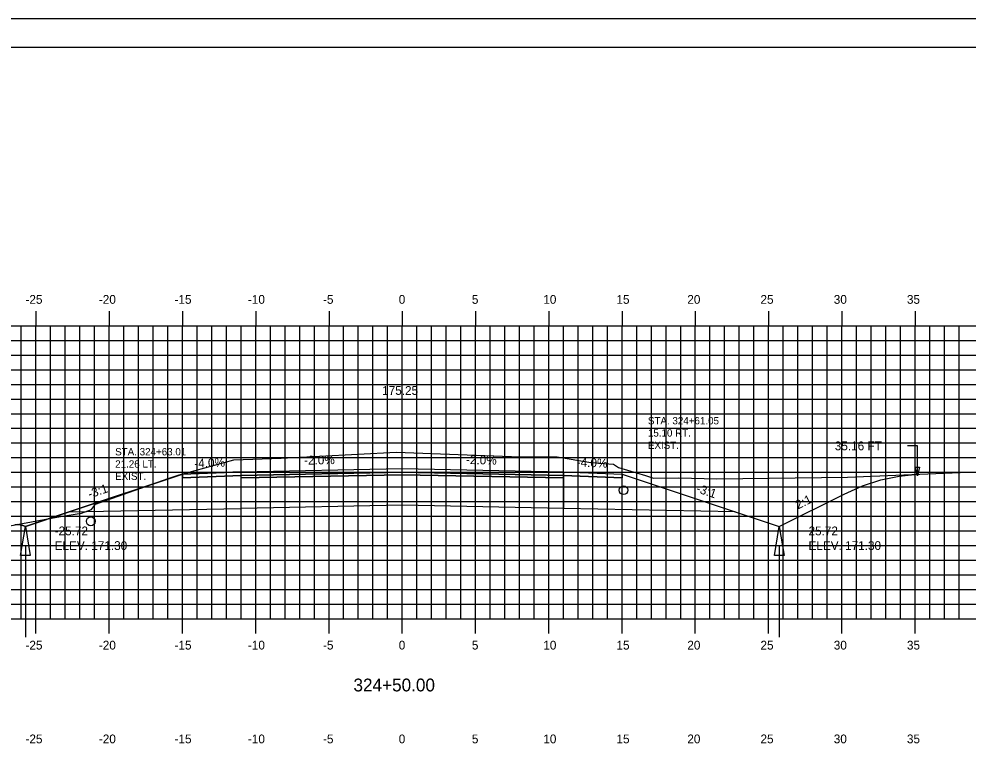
# Model space of a CAD drawing. Extents: x 1140315 to 1140485, y 608981 to 609091.
# Drawn here: x 1140372.3 to 1140437.1, y 609041.6 to 609091.3 of the extents above; entities that cross this region are included whole.
import ezdxf

# ---------------------------------------------------------------- set-up
doc = ezdxf.new("R2010")
doc.units = 0
for name, color, linetype in [('ANNOTATION', 7, 'Continuous'), ('BORDER', 7, 'Continuous'), ('D_Drainage_Ditch_Line', 7, 'Continuous'), ('D_Roadway_Centerline', 7, 'Continuous'), ('D_Roadway_Centerline_Text', 7, 'Continuous'), ('D_Roadway_Edge_Shoulder', 7, 'Continuous'), ('D_Roadway_Edge_TW', 7, 'Continuous'), ('D_Roadway_Pavement', 7, 'Continuous'), ('D_Roadway_SlopeLines', 7, 'Continuous'), ('D_Roadway_SubGrade', 7, 'Continuous'), ('D_Text_Monospaced', 7, 'Continuous'), ('D_Text_Standard', 7, 'Continuous'), ('H_V ANNOTATION', 7, 'Continuous'), ('MAJOR', 7, 'Continuous'), ('MINOR', 7, 'Continuous'), ('PLOT BOUNDARY', 7, 'Continuous'), ('S_Drainage_Invert', 7, 'Continuous'), ('S_Roadway_Centerline', 7, 'Continuous')]:
    doc.layers.add(name, color=color, linetype=linetype)

msp = doc.modelspace()

# ---------------------------------------------------------------- linework, layer by layer
msp.add_lwpolyline([(1140372.049, 609056.744), (1140372.227, 609056.762), (1140372.406, 609056.749), (1140372.585, 609056.706), (1140372.763, 609056.632), (1140375.763, 609057.632), (1140383.487, 609060.206), (1140383.488, 609060.206), (1140387.488, 609060.366), (1140398.488, 609060.586), (1140409.488, 609060.366), (1140413.488, 609060.206), (1140421.211, 609057.632), (1140424.211, 609056.632), (1140428.647, 609058.85), (1140429.897, 609059.403), (1140431.147, 609059.813), (1140432.397, 609060.079), (1140433.647, 609060.201)])
at = {"layer": 'BORDER'}
msp.add_lwpolyline([(1140323.488, 608984.335), (1140483.488, 608984.335), (1140483.488, 609089.335), (1140323.488, 609089.335)], close=True, dxfattribs=at)
at = {"layer": 'D_Drainage_Ditch_Line'}
for p, q in [((1140372.763, 609055.32), (1140372.763, 609049.076)), ((1140424.212, 609055.32), (1140424.211, 609049.076))]:
    msp.add_line(p, q, dxfattribs=at)
for points in [[(1140373.091, 609054.663), (1140372.435, 609054.663), (1140372.763, 609056.632)], [(1140424.54, 609054.663), (1140423.883, 609054.663), (1140424.211, 609056.632)]]:
    msp.add_lwpolyline(points, close=True, dxfattribs=at)
at = {"layer": 'D_Roadway_Edge_Shoulder'}
for points in [[(1140387.488, 609060.366), (1140383.488, 609060.206), (1140383.488, 609059.956), (1140387.488, 609060.116)], [(1140409.488, 609060.366), (1140413.488, 609060.206), (1140413.488, 609059.956), (1140409.488, 609060.116)]]:
    msp.add_lwpolyline(points, close=True, dxfattribs=at)
at = {"layer": 'D_Roadway_Edge_TW'}
msp.add_lwpolyline([(1140387.488, 609060.116), (1140387.488, 609060.366), (1140398.488, 609060.586), (1140409.488, 609060.366), (1140409.488, 609060.116), (1140398.488, 609060.336)], close=True, dxfattribs=at)
at = {"layer": 'D_Roadway_Pavement'}
msp.add_lwpolyline([(1140387.488, 609059.95), (1140387.488, 609060.116), (1140398.488, 609060.336), (1140409.488, 609060.116), (1140409.488, 609059.95), (1140398.488, 609060.17)], close=True, dxfattribs=at)
at = {"layer": 'D_Roadway_SlopeLines'}
for points in [[(1140424.211, 609056.632), (1140428.647, 609058.85), (1140429.897, 609059.403), (1140431.147, 609059.813), (1140432.397, 609060.079), (1140433.647, 609060.201)], [(1140375.763, 609057.632), (1140372.763, 609056.632)], [(1140421.211, 609057.632), (1140424.211, 609056.632)], [(1140372.763, 609056.632), (1140372.585, 609056.706), (1140372.406, 609056.749), (1140372.227, 609056.762), (1140372.049, 609056.744)]]:
    msp.add_lwpolyline(points, dxfattribs=at)
at = {"layer": 'D_Roadway_SubGrade'}
for points in [[(1140387.488, 609059.95), (1140387.488, 609060.116), (1140383.488, 609059.956), (1140383.488, 609060.206), (1140383.487, 609060.206), (1140375.763, 609057.632), (1140387.488, 609057.866)], [(1140387.488, 609057.866), (1140387.488, 609059.95), (1140398.488, 609060.17), (1140409.488, 609059.95), (1140409.488, 609057.866), (1140398.488, 609058.086)], [(1140409.488, 609059.95), (1140409.488, 609060.116), (1140413.488, 609059.956), (1140413.488, 609060.206), (1140413.488, 609060.206), (1140421.211, 609057.632), (1140409.488, 609057.866)]]:
    msp.add_lwpolyline(points, close=True, dxfattribs=at)
at = {"layer": 'D_Text_Standard'}
msp.add_lwpolyline([(1140433.647, 609060.1), (1140433.648, 609062.138), (1140432.968, 609062.138)], dxfattribs=at)
msp.add_lwpolyline([(1140433.647, 609060.1), (1140433.501, 609060.682), (1140433.793, 609060.682)], close=True, dxfattribs=at)
at = {"layer": 'MAJOR'}
for p, q in [((1140373.488, 609071.337), (1140373.488, 609070.335)), ((1140378.488, 609071.337), (1140378.488, 609070.335)), ((1140383.488, 609071.337), (1140383.488, 609070.335)), ((1140388.488, 609071.337), (1140388.488, 609070.335)), ((1140393.488, 609071.337), (1140393.488, 609070.335)), ((1140398.488, 609071.337), (1140398.488, 609070.335)), ((1140403.488, 609071.337), (1140403.488, 609070.335)), ((1140408.488, 609071.337), (1140408.488, 609070.335)), ((1140413.488, 609071.337), (1140413.488, 609070.335)), ((1140418.488, 609071.337), (1140418.488, 609070.335)), ((1140423.488, 609071.337), (1140423.488, 609070.335)), ((1140428.488, 609071.337), (1140428.488, 609070.335)), ((1140433.488, 609071.337), (1140433.488, 609070.335)), ((1140328.488, 609070.335), (1140468.488, 609070.335)), ((1140328.488, 609070.335), (1140468.488, 609070.335)), ((1140373.488, 609050.335), (1140373.488, 609070.335)), ((1140378.488, 609050.335), (1140378.488, 609070.335)), ((1140383.488, 609050.335), (1140383.488, 609070.335)), ((1140388.488, 609050.335), (1140388.488, 609070.335)), ((1140393.488, 609050.335), (1140393.488, 609070.335)), ((1140398.488, 609050.335), (1140398.488, 609070.335)), ((1140403.488, 609050.335), (1140403.488, 609070.335)), ((1140408.488, 609050.335), (1140408.488, 609070.335)), ((1140413.488, 609050.335), (1140413.488, 609070.335)), ((1140418.488, 609050.335), (1140418.488, 609070.335)), ((1140423.488, 609050.335), (1140423.488, 609070.335)), ((1140428.488, 609050.335), (1140428.488, 609070.335)), ((1140433.488, 609050.335), (1140433.488, 609070.335)), ((1140328.488, 609065.335), (1140468.488, 609065.335)), ((1140328.488, 609060.335), (1140468.488, 609060.335)), ((1140328.488, 609055.335), (1140468.488, 609055.335)), ((1140328.488, 609050.335), (1140468.488, 609050.335)), ((1140328.488, 609050.335), (1140468.488, 609050.335)), ((1140373.488, 609049.333), (1140373.488, 609050.335)), ((1140378.488, 609049.333), (1140378.488, 609050.335)), ((1140383.488, 609049.333), (1140383.488, 609050.335)), ((1140388.488, 609049.333), (1140388.488, 609050.335)), ((1140393.488, 609049.333), (1140393.488, 609050.335)), ((1140398.488, 609049.333), (1140398.488, 609050.335)), ((1140403.488, 609049.333), (1140403.488, 609050.335)), ((1140408.488, 609049.333), (1140408.488, 609050.335)), ((1140413.488, 609049.333), (1140413.488, 609050.335)), ((1140418.488, 609049.333), (1140418.488, 609050.335)), ((1140423.488, 609049.333), (1140423.488, 609050.335)), ((1140428.488, 609049.333), (1140428.488, 609050.335)), ((1140433.488, 609049.333), (1140433.488, 609050.335))]:
    msp.add_line(p, q, dxfattribs=at)
at = {"layer": 'MINOR'}
for p, q in [((1140372.488, 609050.335), (1140372.488, 609070.335)), ((1140374.488, 609050.335), (1140374.488, 609070.335)), ((1140375.488, 609050.335), (1140375.488, 609070.335)), ((1140376.488, 609050.335), (1140376.488, 609070.335)), ((1140377.488, 609050.335), (1140377.488, 609070.335)), ((1140379.488, 609050.335), (1140379.488, 609070.335)), ((1140380.488, 609050.335), (1140380.488, 609070.335)), ((1140381.488, 609050.335), (1140381.488, 609070.335)), ((1140382.488, 609050.335), (1140382.488, 609070.335)), ((1140384.488, 609050.335), (1140384.488, 609070.335)), ((1140385.488, 609050.335), (1140385.488, 609070.335)), ((1140386.488, 609050.335), (1140386.488, 609070.335)), ((1140387.488, 609050.335), (1140387.488, 609070.335)), ((1140389.488, 609050.335), (1140389.488, 609070.335)), ((1140390.488, 609050.335), (1140390.488, 609070.335)), ((1140391.488, 609050.335), (1140391.488, 609070.335)), ((1140392.488, 609050.335), (1140392.488, 609070.335)), ((1140394.488, 609050.335), (1140394.488, 609070.335)), ((1140395.488, 609050.335), (1140395.488, 609070.335)), ((1140396.488, 609050.335), (1140396.488, 609070.335)), ((1140397.488, 609050.335), (1140397.488, 609070.335)), ((1140399.488, 609050.335), (1140399.488, 609070.335)), ((1140400.488, 609050.335), (1140400.488, 609070.335)), ((1140401.488, 609050.335), (1140401.488, 609070.335)), ((1140402.488, 609050.335), (1140402.488, 609070.335)), ((1140404.488, 609050.335), (1140404.488, 609070.335)), ((1140405.488, 609050.335), (1140405.488, 609070.335)), ((1140406.488, 609050.335), (1140406.488, 609070.335)), ((1140407.488, 609050.335), (1140407.488, 609070.335)), ((1140409.488, 609050.335), (1140409.488, 609070.335)), ((1140410.488, 609050.335), (1140410.488, 609070.335)), ((1140411.488, 609050.335), (1140411.488, 609070.335)), ((1140412.488, 609050.335), (1140412.488, 609070.335)), ((1140414.488, 609050.335), (1140414.488, 609070.335)), ((1140415.488, 609050.335), (1140415.488, 609070.335)), ((1140416.488, 609050.335), (1140416.488, 609070.335)), ((1140417.488, 609050.335), (1140417.488, 609070.335)), ((1140419.488, 609050.335), (1140419.488, 609070.335)), ((1140420.488, 609050.335), (1140420.488, 609070.335)), ((1140421.488, 609050.335), (1140421.488, 609070.335)), ((1140422.488, 609050.335), (1140422.488, 609070.335)), ((1140424.488, 609050.335), (1140424.488, 609070.335)), ((1140425.488, 609050.335), (1140425.488, 609070.335)), ((1140426.488, 609050.335), (1140426.488, 609070.335)), ((1140427.488, 609050.335), (1140427.488, 609070.335)), ((1140429.488, 609050.335), (1140429.488, 609070.335)), ((1140430.488, 609050.335), (1140430.488, 609070.335)), ((1140431.488, 609050.335), (1140431.488, 609070.335)), ((1140432.488, 609050.335), (1140432.488, 609070.335)), ((1140434.488, 609050.335), (1140434.488, 609070.335)), ((1140435.488, 609050.335), (1140435.488, 609070.335)), ((1140436.488, 609050.335), (1140436.488, 609070.335)), ((1140328.488, 609069.335), (1140468.488, 609069.335)), ((1140328.488, 609068.335), (1140468.488, 609068.335)), ((1140328.488, 609067.335), (1140468.488, 609067.335)), ((1140328.488, 609066.335), (1140468.488, 609066.335)), ((1140328.488, 609064.335), (1140468.488, 609064.335)), ((1140328.488, 609063.335), (1140468.488, 609063.335)), ((1140328.488, 609062.335), (1140468.488, 609062.335)), ((1140328.488, 609061.335), (1140468.488, 609061.335)), ((1140328.488, 609059.335), (1140468.488, 609059.335)), ((1140328.488, 609058.335), (1140468.488, 609058.335)), ((1140328.488, 609057.335), (1140468.488, 609057.335)), ((1140328.488, 609056.335), (1140468.488, 609056.335)), ((1140328.488, 609054.335), (1140468.488, 609054.335)), ((1140328.488, 609053.335), (1140468.488, 609053.335)), ((1140328.488, 609052.335), (1140468.488, 609052.335)), ((1140328.488, 609051.335), (1140468.488, 609051.335))]:
    msp.add_line(p, q, dxfattribs=at)
at = {"layer": 'PLOT BOUNDARY'}
msp.add_lwpolyline([(1140315.395, 608981.276), (1140485.395, 608981.276), (1140485.395, 609091.276), (1140315.395, 609091.276)], close=True, dxfattribs=at)
at = {"layer": 'S_Drainage_Invert'}
for centre in [(1140413.585, 609059.107), (1140377.227, 609056.988)]:
    msp.add_circle(centre, 0.3, dxfattribs=at)
at = {"layer": 'S_Roadway_Centerline'}
msp.add_lwpolyline([(1140368.956, 609056.168), (1140375.166, 609057.325), (1140376.592, 609057.541), (1140377.277, 609057.792), (1140377.554, 609058.165), (1140382.514, 609059.91), (1140383.263, 609060.167), (1140383.704, 609060.271), (1140386.994, 609061.174), (1140390.217, 609061.308), (1140398.07, 609061.704), (1140405.943, 609061.414), (1140409.064, 609061.381), (1140411.348, 609060.996), (1140412.9, 609060.895), (1140413.245, 609060.66), (1140415.077, 609060.121), (1140415.631, 609059.932), (1140417.362, 609059.96), (1140419.951, 609059.88), (1140428.868, 609060.007), (1140437.102, 609060.342), (1140459.468, 609061.257), (1140467.056, 609061.448)], dxfattribs=at)

# ---------------------------------------------------------------- texts
at = {"layer": 'ANNOTATION'}
for s, rotation, p in [('-4.0%', 2.29061, (1140384.304, 609060.64)), ('-2.0%', 1.14576, (1140391.791, 609060.853)), ('-2.0%', 358.85424, (1140402.831, 609060.9)), ('-4.0%', 357.70939, (1140410.384, 609060.731)), ('-3:1', 18.43482, (1140377.142, 609058.546)), ('-3:1', 341.56521, (1140418.499, 609058.99)), ('2:1', 26.56505, (1140425.502, 609057.795))]:
    msp.add_text(s, height=0.6, rotation=rotation, dxfattribs=at).set_placement(p)
at = {"layer": 'D_Roadway_Centerline'}
for s, p in [('C', (1140398.483, 609060.586)), ('L', (1140398.488, 609060.579))]:
    msp.add_text(s, height=0.0146, dxfattribs=at).set_placement(p)
at = {"layer": 'D_Roadway_Centerline_Text'}
msp.add_text('175.25', height=0.6, dxfattribs=at).set_placement((1140397.115, 609065.618))
at = {"layer": 'D_Text_Monospaced'}
for s, height, p in [('STA. 324+61.05', 0.49998, (1140415.252, 609063.605)), ('15.10 RT.', 0.5, (1140415.252, 609062.771)), ('STA. 324+63.01', 0.49998, (1140378.894, 609061.486)), ('EXIST. ', 0.5, (1140415.252, 609061.931)), ('21.26 LT.', 0.5, (1140378.894, 609060.652)), ('EXIST. ', 0.5, (1140378.894, 609059.812))]:
    msp.add_text(s, height=height, dxfattribs=at).set_placement(p)
at = {"layer": 'D_Text_Standard'}
for s, p in [('35.16 FT', (1140428.005, 609061.838)), ('-25.72', (1140374.763, 609056.032)), ('25.72', (1140426.212, 609056.032)), ('ELEV. 171.30', (1140374.763, 609055.03)), ('ELEV. 171.30', (1140426.212, 609055.03))]:
    msp.add_text(s, height=0.6, dxfattribs=at).set_placement(p)
at = {"layer": 'H_V ANNOTATION'}
for s, height, p in [('-25', 0.6, (1140372.773, 609071.835)), ('-20', 0.6, (1140377.781, 609071.835)), ('-15', 0.6, (1140382.945, 609071.835)), ('-10', 0.6, (1140387.953, 609071.835)), ('-5', 0.6, (1140393.079, 609071.835)), ('0', 0.6, (1140398.247, 609071.835)), ('5', 0.6, (1140403.239, 609071.835)), ('10', 0.6, (1140408.113, 609071.835)), ('15', 0.6, (1140413.105, 609071.835)), ('20', 0.6, (1140417.942, 609071.835)), ('25', 0.6, (1140422.934, 609071.835)), ('30', 0.6, (1140427.937, 609071.835)), ('35', 0.6, (1140432.929, 609071.835)), ('-25', 0.6, (1140372.773, 609048.235)), ('-20', 0.6, (1140377.781, 609048.235)), ('-15', 0.6, (1140382.945, 609048.235)), ('-10', 0.6, (1140387.953, 609048.235)), ('-5', 0.6, (1140393.079, 609048.235)), ('0', 0.6, (1140398.247, 609048.235)), ('5', 0.6, (1140403.239, 609048.235)), ('10', 0.6, (1140408.113, 609048.235)), ('15', 0.6, (1140413.105, 609048.235)), ('20', 0.6, (1140417.942, 609048.235)), ('25', 0.6, (1140422.934, 609048.235)), ('30', 0.6, (1140427.937, 609048.235)), ('35', 0.6, (1140432.929, 609048.235)), ('324+50.00', 0.875, (1140395.156, 609045.378)), ('-25', 0.6, (1140372.773, 609041.835)), ('-20', 0.6, (1140377.781, 609041.835)), ('-15', 0.6, (1140382.945, 609041.835)), ('-10', 0.6, (1140387.953, 609041.835)), ('-5', 0.6, (1140393.079, 609041.835)), ('0', 0.6, (1140398.247, 609041.835)), ('5', 0.6, (1140403.239, 609041.835)), ('10', 0.6, (1140408.113, 609041.835)), ('15', 0.6, (1140413.105, 609041.835)), ('20', 0.6, (1140417.942, 609041.835)), ('25', 0.6, (1140422.934, 609041.835)), ('30', 0.6, (1140427.937, 609041.835)), ('35', 0.6, (1140432.929, 609041.835))]:
    msp.add_text(s, height=height, dxfattribs=at).set_placement(p)
at = {"layer": 'S_Roadway_Centerline'}
for s, p in [('L', (1140398.061, 609061.697)), ('C', (1140398.064, 609061.704))]:
    msp.add_text(s, height=0.0146, dxfattribs=at).set_placement(p)

doc.saveas('drawing.dxf')
